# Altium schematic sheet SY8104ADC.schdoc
size 127 x 101 mm
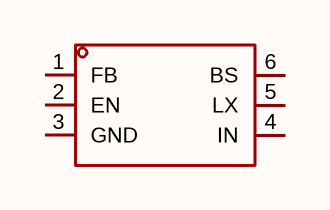
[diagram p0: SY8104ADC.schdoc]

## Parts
U?  sy8104adc  [SOT-23-6_L2.9-W1.6-P0.95-LS2.8-BR]  (value not drawn)

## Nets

Not connected (* = marked no-connect by the designer): U? 1(FB) 2(EN) 3(GND) 4(IN) 5(LX) 6(BS)

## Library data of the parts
U? = sy8104adc: 功能类型:降压型;工作电压:4.5V~18V;输出电压:-;输出电流:4A;输出类型:可调;; Manufacturer: Silergy(矽力杰); AddInBom: yes; ModelId: 18da8f6c14a34920b3e136b5c401a119; ModelName: SOT-23-6_L2.9-W1.6-H1.5-LS2.8-P0.95; ModelTransform: 110.73671,114.173,0,180,0,0,0.001,-0.003,0; Function: 降压型; Output Current: 4A; Frequency - Switching: 500kHz; Synchronous Rectifier: 是; Number of Outputs: 1; Topology: 降压式; Quiescent Current: 100uA; Switch tube (built-in/external): 内置; Output Type: 可调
